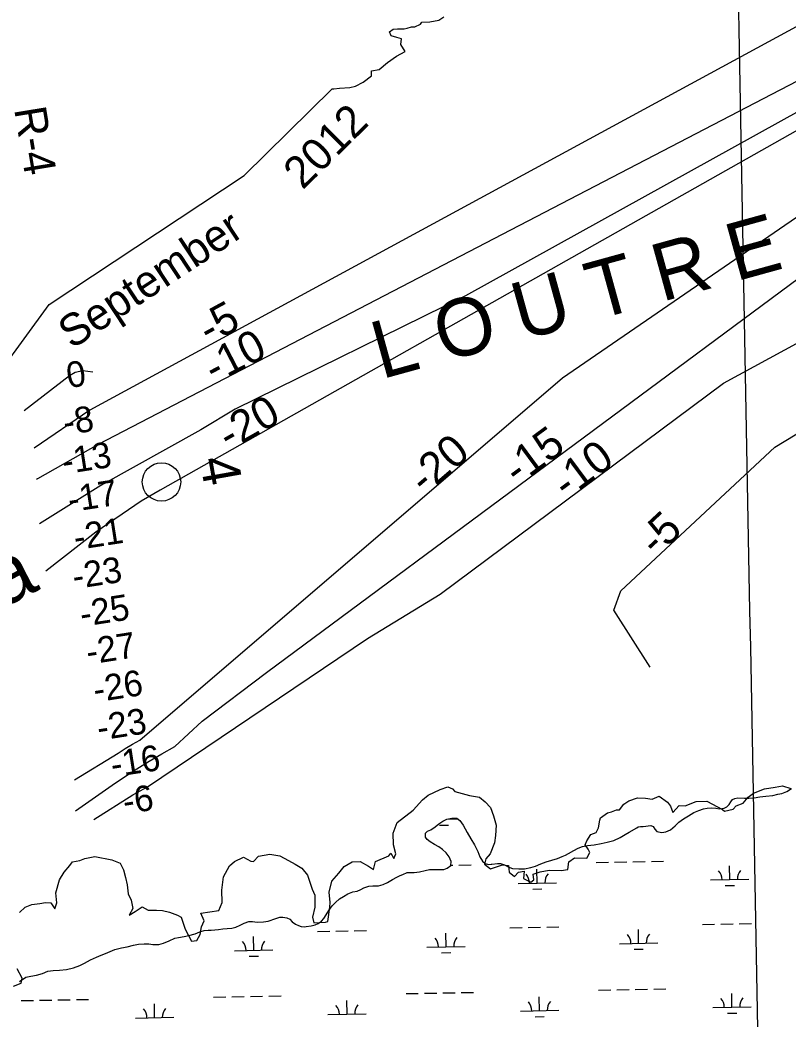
# Model space of a CAD drawing. Extents: x 3957609 to 3995875, y 234277 to 260273.
# Drawn here: x 3965192 to 3967195, y 243942 to 246545 of the extents above; entities that cross this region are included whole.
import ezdxf

# ---------------------------------------------------------------- set-up
doc = ezdxf.new("R2010")
doc.units = 0
for name, color, linetype in [('V-GRID-MAJR', 7, 'Continuous'), ('V-RIVR-EDGE', 7, 'Continuous'), ('V-RIVR-IDEN', 7, 'Continuous'), ('V-RIVR-MILE', 7, 'Continuous'), ('V-RIVR-RANG', 7, 'Continuous'), ('V-RIVR-RANG-IDEN', 7, 'Continuous'), ('V-TOPO-MINR', 7, 'Continuous'), ('V-TOPO-MINR-IDEN', 7, 'Continuous'), ('V-TOPO-WATR', 7, 'Continuous'), ('V-WETL-SWMP', 7, 'Continuous')]:
    doc.layers.add(name, color=color, linetype=linetype)

msp = doc.modelspace()

# ---------------------------------------------------------------- linework, layer by layer
at = {"layer": 'V-GRID-MAJR'}
msp.add_spline([(3967193.104, 239799.451), (3967136.284, 242827.44), (3967022.571, 248887.277), (3966908.859, 254947.105), (3966851.966, 257978.948)], degree=3, dxfattribs=at)
at = {"layer": 'V-RIVR-EDGE'}
for points in [[(3966005.912, 246365.573), (3966010.265, 246366.195), (3966025.234, 246367.858), (3966051.845, 246369.521), (3966066.814, 246372.848), (3966086.773, 246382.827), (3966108.395, 246399.459), (3966108.395, 246412.765), (3966128.354, 246416.092), (3966149.976, 246434.387), (3966173.261, 246451.019), (3966196.546, 246462.662), (3966184.903, 246480.957), (3966186.567, 246495.926), (3966174.924, 246499.253), (3966159.955, 246504.243), (3966154.965, 246514.222), (3966164.945, 246520.875), (3966176.587, 246522.538), (3966193.22, 246522.538), (3966201.536, 246524.201), (3966213.178, 246527.528), (3966221.494, 246527.528), (3966236.464, 246534.181), (3966239.79, 246539.17), (3966260.58, 246540.002), (3966283.866, 246544.992), (3966297.171, 246553.308)], [(3964136.99, 244658.589), (3964156.12, 244665.056), (3964172.018, 244677.72), (3964177.945, 244686.611), (3964517.715, 245044.972), (3964910.025, 245389.861), (3965078.158, 245545.06), (3965267.847, 245803.727), (3965776.558, 246139.993), (3966005.855, 246365.518)], [(3965190.824, 244219.454), (3965205.027, 244232.71), (3965223.017, 244240.285), (3965243.848, 244242.179), (3965258.051, 244245.019), (3965272.254, 244244.072), (3965282.67, 244228.923), (3965288.351, 244244.072), (3965285.511, 244270.585), (3965294.979, 244304.672), (3965307.288, 244324.556), (3965321.491, 244341.6), (3965329.066, 244351.068), (3965348.004, 244354.856), (3965361.26, 244359.59), (3965386.825, 244365.271), (3965431.328, 244356.749), (3965453.106, 244347.281), (3965461.627, 244330.237), (3965467.309, 244310.353), (3965471.096, 244291.416), (3965473.937, 244267.744), (3965481.512, 244251.647), (3965486.246, 244229.87), (3965476.777, 244211.879), (3965491.927, 244221.348), (3965510.864, 244233.657), (3965526.014, 244225.135), (3965547.792, 244225.135), (3965563.889, 244224.188), (3965581.879, 244220.401), (3965602.71, 244211.879), (3965612.179, 244207.145), (3965622.594, 244175.898), (3965638.691, 244144.652), (3965652.894, 244146.545), (3965661.416, 244161.695), (3965665.203, 244181.579), (3965671.831, 244197.676), (3965663.31, 244217.56), (3965710.653, 244224.188), (3965719.175, 244245.019), (3965718.228, 244277.213), (3965722.962, 244312.247), (3965738.112, 244340.653), (3965751.368, 244352.015), (3965775.04, 244363.377), (3965793.977, 244352.962), (3965800.605, 244352.015), (3965813.861, 244366.218), (3965843.214, 244370.952), (3965869.726, 244367.165), (3965892.451, 244354.856), (3965909.495, 244345.387), (3965926.538, 244334.972), (3965941.688, 244316.034), (3965953.997, 244280.053), (3965960.625, 244263.957), (3965960.625, 244232.71), (3965954.944, 244207.145), (3965957.785, 244191.995), (3965988.084, 244193.889), (3965994.712, 244195.782), (3965999.447, 244232.71), (3966000.394, 244245.019), (3965998.5, 244272.478), (3966005.128, 244300.884), (3966023.118, 244321.715), (3966037.321, 244338.759), (3966058.152, 244351.068), (3966078.983, 244352.015), (3966100.761, 244339.706), (3966114.017, 244331.184), (3966118.752, 244352.015), (3966153.786, 244367.165), (3966158.52, 244373.793), (3966167.042, 244359.59), (3966171.776, 244371.899), (3966166.095, 244395.571), (3966165.148, 244425.871), (3966175.564, 244453.33), (3966217.226, 244485.523), (3966241.844, 244512.982), (3966256.047, 244525.291), (3966287.294, 244539.494), (3966307.178, 244547.069), (3966319.487, 244541.388), (3966326.115, 244534.76), (3966363.99, 244524.345), (3966390.502, 244519.61), (3966404.705, 244507.301), (3966418.908, 244493.098), (3966426.483, 244471.32), (3966433.111, 244446.702), (3966432.164, 244420.189), (3966429.323, 244400.305), (3966417.961, 244371.899), (3966406.599, 244358.643), (3966402.811, 244345.387), (3966418.908, 244333.078), (3966450.155, 244343.493), (3966465.304, 244341.6), (3966467.198, 244324.556), (3966481.401, 244313.194), (3966491.817, 244324.556), (3966506.966, 244326.45), (3966505.073, 244307.512), (3966524.01, 244298.044), (3966531.585, 244304.672), (3966529.691, 244318.875), (3966548.628, 244325.503), (3966571.353, 244329.29), (3966602.6, 244328.343), (3966620.59, 244331.184), (3966623.431, 244351.068), (3966637.634, 244361.484), (3966669.827, 244360.537), (3966677.402, 244375.687), (3966673.654, 244384.121)], [(3966673.649, 244384.181), (3966666.04, 244395.571), (3966669.827, 244405.986), (3966680.243, 244422.083), (3966694.446, 244427.764), (3966700.127, 244440.074), (3966703.914, 244459.958), (3966705.808, 244465.639), (3966723.799, 244478.895), (3966734.214, 244481.736), (3966747.47, 244486.47), (3966755.045, 244486.47), (3966766.407, 244501.62), (3966779.664, 244510.142), (3966802.388, 244517.716), (3966823.219, 244516.77), (3966840.263, 244514.876), (3966858.253, 244522.451), (3966880.031, 244506.354), (3966888.553, 244495.939), (3966894.234, 244479.842), (3966910.331, 244497.832), (3966926.428, 244496.885), (3966954.834, 244508.248), (3966983.24, 244509.195), (3967023.955, 244487.417), (3967028.689, 244483.629), (3967051.414, 244488.364), (3967058.989, 244496.885), (3967077.926, 244504.46), (3967090.235, 244519.61), (3967104.438, 244530.026), (3967132.844, 244541.388), (3967161.25, 244546.122), (3967180.187, 244548.963), (3967201.965, 244542.335)], [(3965174.727, 244027.24), (3965194.611, 244034.815), (3965197.452, 244048.071), (3965184.196, 244072.69)]]:
    msp.add_lwpolyline(points, dxfattribs=at)
at = {"layer": 'V-RIVR-MILE'}
msp.add_circle((3965560.875, 245341.194), 50, dxfattribs=at)
at = {"layer": 'V-TOPO-MINR'}
for points in [[(3968181.084, 247052.195), (3965373.926, 245528.563), (3965228.884, 245429.671)], [(3968096.001, 246842.324), (3965395.806, 245438.803), (3965237.649, 245349.708), (3965234.899, 245347.738)], [(3968197.612, 246811.081), (3965557.117, 245319.444), (3965507.466, 245290.941), (3965389.501, 245210.055), (3965258.871, 245108.954)], [(3968102.887, 246796.068), (3966353.197, 245826.642), (3965752.679, 245530.856), (3965663.169, 245477.445), (3965402.799, 245332.334), (3965242.482, 245232.395)], [(3965334.242, 244565.003), (3965447.5, 244634.66), (3965466.336, 244646.125), (3965485.243, 244657.472), (3965504.253, 244668.644), (3966606.154, 245612.18), (3967724.041, 246379.376), (3967996.583, 246490.295), (3968090.356, 246510.845)], [(3965336.203, 244483.843), (3965432.433, 244550.968), (3965464.151, 244572.47), (3965496.234, 244593.396), (3965528.864, 244613.459), (3965561.858, 244632.947), (3965595.241, 244651.79), (3965666.539, 244717.388), (3965834.719, 244844.984), (3967345.253, 245963.426), (3967871.86, 246268.456), (3968018.214, 246314.387)], [(3965384.711, 244461.903), (3965486.509, 244525.473), (3965495.836, 244531.125), (3965505.26, 244536.606), (3965514.828, 244541.832), (3965524.491, 244546.886), (3966098.023, 244932.795), (3966287.417, 245048.337), (3967026.516, 245598.315), (3967816.428, 246028.129), (3967984.26, 246085.689)], [(3966834.79, 244858.74), (3966740.115, 245006.742), (3966758.593, 245057.58), (3967160.478, 245431.935), (3967617.795, 245709.235), (3967862.622, 245806.289), (3967993.694, 245839.928)]]:
    msp.add_lwpolyline(points, dxfattribs=at)
at = {"layer": 'V-TOPO-WATR'}
msp.add_lwpolyline([(3965202.7, 245527.494), (3965320.783, 245618.904), (3965335.436, 245627.527), (3965355.709, 245631.981), (3965381.601, 245628.133)], dxfattribs=at)
at = {"layer": 'V-WETL-SWMP'}
for p, q in [((3966285.366, 244446.642), (3966309.362, 244447.078)), ((3966304.097, 244462.416), (3966333.362, 244462.948)), ((3966314.998, 244342.523), (3966320.419, 244342.622)), ((3966336.416, 244342.913), (3966368.411, 244343.495)), ((3966694.265, 244349.42), (3966726.259, 244350.001)), ((3966742.257, 244350.292), (3966774.252, 244350.874)), ((3966790.249, 244351.165), (3966822.244, 244351.747)), ((3966838.241, 244352.038), (3966870.236, 244352.619)), ((3967042.446, 244305), (3967041.791, 244340.994)), ((3966540.621, 244295.876), (3966539.966, 244331.87)), ((3966490.629, 244294.967), (3966590.613, 244296.785)), ((3966992.454, 244304.091), (3967092.438, 244305.909)), ((3967030.728, 244289.354), (3967054.724, 244289.79)), ((3966528.903, 244280.229), (3966552.899, 244280.665)), ((3966469.323, 244179.128), (3966501.318, 244179.71)), ((3966517.316, 244180.001), (3966549.31, 244180.582)), ((3966565.308, 244180.873), (3966597.302, 244181.455)), ((3966971.149, 244188.253), (3967003.143, 244188.835)), ((3967019.141, 244189.125), (3967051.135, 244189.707)), ((3967067.133, 244189.998), (3967099.127, 244190.58)), ((3965801.306, 244120.544), (3965800.652, 244156.538)), ((3965967.498, 244170.003), (3965999.493, 244170.585)), ((3966015.491, 244170.876), (3966047.485, 244171.458)), ((3966063.483, 244171.749), (3966095.477, 244172.33)), ((3966303.131, 244129.669), (3966302.477, 244165.663)), ((3966804.956, 244138.793), (3966804.302, 244174.787)), ((3966253.139, 244128.76), (3966353.123, 244130.578)), ((3966754.965, 244137.884), (3966854.948, 244139.702)), ((3965751.314, 244119.635), (3965851.298, 244121.453)), ((3965789.589, 244104.897), (3965813.585, 244105.334)), ((3966291.414, 244114.022), (3966315.41, 244114.458)), ((3966793.239, 244123.147), (3966817.235, 244123.583)), ((3965696.663, 243998.55), (3965728.657, 243999.132)), ((3965744.655, 243999.423), (3965776.649, 244000.005)), ((3965792.647, 244000.296), (3965824.642, 244000.877)), ((3965840.639, 244001.168), (3965872.634, 244001.75)), ((3966198.488, 244007.675), (3966230.482, 244008.257)), ((3966246.48, 244008.548), (3966278.475, 244009.129)), ((3966294.472, 244009.42), (3966326.467, 244010.002)), ((3966342.464, 244010.293), (3966374.459, 244010.875)), ((3966546.669, 243963.256), (3966546.014, 243999.25)), ((3966700.313, 244016.8), (3966732.308, 244017.381)), ((3966748.305, 244017.672), (3966780.3, 244018.254)), ((3966796.297, 244018.545), (3966828.292, 244019.127)), ((3966844.289, 244019.418), (3966876.284, 244019.999)), ((3967048.494, 243972.38), (3967047.839, 244008.374)), ((3965194.838, 243989.425), (3965226.832, 243990.007)), ((3965242.83, 243990.298), (3965274.824, 243990.88)), ((3965290.822, 243991.171), (3965322.817, 243991.753)), ((3965338.814, 243992.043), (3965370.809, 243992.625)), ((3965543.019, 243945.006), (3965542.364, 243981)), ((3966044.844, 243954.131), (3966044.189, 243990.125)), ((3966998.502, 243971.471), (3967098.486, 243973.289)), ((3965493.027, 243944.097), (3965593.01, 243945.915)), ((3965994.852, 243953.222), (3966094.836, 243955.04)), ((3966496.677, 243962.347), (3966596.661, 243964.165)), ((3966534.951, 243947.609), (3966558.947, 243948.045)), ((3967036.776, 243956.734), (3967060.772, 243957.17))]:
    msp.add_line(p, q, dxfattribs=at)
for points in [[(3966816.722, 244443.577), (3966836.739, 244445.781), (3966842.498, 244443.138), (3966847.107, 244435.961), (3966852.302, 244430.147), (3966865.29, 244427.894), (3966875.976, 244429.08), (3966887.817, 244434.349), (3966900.04, 244445.349), (3966910.18, 244454.213), (3966922.129, 244462.95), (3966934.988, 244471.245), (3966948.75, 244479.702), (3966961.947, 244484.987), (3966974.553, 244489.361), (3966983.574, 244491.129), (3966994.419, 244491.563), (3967006.18, 244491.104), (3967015.54, 244489.711), (3967027.734, 244490.764), (3967035.076, 244494.32), (3967041.329, 244500.576), (3967045.616, 244507.41), (3967050.217, 244513.193), (3967055.755, 244516.275), (3967063.721, 244518.03), (3967080.908, 244517.486), (3967092.814, 244517.481), (3967106.518, 244518.251), (3967121.11, 244520.389), (3967136.914, 244522.089), (3967154.819, 244524.418), (3967167.895, 244527.29), (3967178.118, 244529.374), (3967191.313, 244534.81), (3967203.884, 244542.047)], [(3965925.481, 244182.665), (3965933.625, 244182.162), (3965937.991, 244182.516), (3965950.783, 244184.029), (3965961.599, 244186.874), (3965969.388, 244190.737), (3965977.762, 244196.114), (3965984.151, 244203.576), (3965990.36, 244213.448), (3965996.854, 244224.68), (3966005.602, 244236.391), (3966014.231, 244245.539), (3966025.271, 244254.716), (3966035.594, 244260.87), (3966046.965, 244267.64), (3966059.712, 244272.769), (3966071.138, 244275.019), (3966080.28, 244279.199), (3966088.671, 244283.22), (3966101.427, 244287.596), (3966111.515, 244288.322), (3966126.583, 244288.506), (3966139.204, 244291.675), (3966150.435, 244297.539), (3966163.458, 244304.781), (3966174.535, 244310.944), (3966183.07, 244315.419), (3966189.816, 244318.365), (3966201.512, 244323.18), (3966209.044, 244323.423), (3966219.289, 244323.698), (3966233.282, 244325.527), (3966248.467, 244328.426), (3966259.741, 244330.824), (3966268.626, 244331.385), (3966282.042, 244331.096), (3966296.959, 244331.279), (3966305.963, 244334.403), (3966314.914, 244341.897), (3966316.296, 244352.162), (3966311.029, 244363.852), (3966303.366, 244374.308), (3966293.31, 244383.227), (3966284.181, 244390.349), (3966272.955, 244396.391), (3966261.872, 244403.037), (3966253.809, 244409.268), (3966249.209, 244415.692), (3966249.084, 244425.939), (3966254.602, 244430.678), (3966262.842, 244434.697), (3966274.201, 244442.371), (3966283.896, 244450.628), (3966294.06, 244457.534), (3966304.547, 244462.635), (3966318.079, 244465.212), (3966330.743, 244464.764), (3966338.647, 244459.284), (3966347.24, 244446.73), (3966357.869, 244427.871), (3966367.566, 244411.262), (3966377.249, 244395.857), (3966386.055, 244378.182), (3966390.594, 244364.373), (3966398.121, 244352.71), (3966404.823, 244346.914), (3966413.148, 244344.002), (3966420.819, 244345.15), (3966422.477, 244345.171), (3966436.623, 244346.851), (3966444.759, 244346.95), (3966455.05, 244343.459), (3966465.216, 244337.856), (3966476.565, 244334.077), (3966492.857, 244332.769), (3966507.319, 244333.247), (3966523.555, 244336.46), (3966536.323, 244339.931), (3966550.27, 244345.527), (3966563.765, 244351.117), (3966578.93, 244355.673), (3966593.495, 244360.071), (3966605.492, 244364.889), (3966614.039, 244368.46), (3966622.424, 244372.933), (3966636.343, 244380.789), (3966647.12, 244386.798), (3966658.521, 244391.157), (3966671.303, 244393.423), (3966688.756, 244395.746), (3966707.104, 244398.834), (3966722.738, 244402.039), (3966740.16, 244406.924), (3966756.493, 244414.659), (3966769.659, 244422.506), (3966780.736, 244428.669), (3966800.489, 244440.063), (3966803.78, 244442.062), (3966809.64, 244443.49), (3966816.722, 244443.577)], [(3965190.286, 244039.552), (3965206.734, 244050.152), (3965219.81, 244053.024), (3965235.301, 244055.625), (3965250.163, 244060.328), (3965264.711, 244066.082), (3965278.096, 244068.355), (3965294.974, 244068.411), (3965313.032, 244070.59), (3965331.662, 244075.339), (3965348.02, 244080.965), (3965360.3, 244087.294), (3965375.868, 244095.923), (3965391.007, 244102.589), (3965403.903, 244107.87), (3965414.848, 244112.525), (3965439.585, 244123.075), (3965456.568, 244126.9), (3965471.451, 244129.945), (3965487.829, 244133.913), (3965501.059, 244136.486), (3965515.813, 244137.721), (3965527.877, 244137.115), (3965537.842, 244135.579), (3965553.965, 244135.776), (3965566.433, 244139.093), (3965580.52, 244145.595), (3965595.211, 244151.954), (3965605.132, 244154.034), (3965619.574, 244156.17), (3965632.35, 244158.888), (3965648.422, 244163.304), (3965660.416, 244168.424), (3965672.126, 244172.033), (3965682.966, 244172.919), (3965690.046, 244173.156), (3965709.472, 244174.449), (3965720.749, 244176.546), (3965731.89, 244177.435), (3965744.393, 244177.89), (3965754.757, 244180.729), (3965765.841, 244186.29), (3965776.028, 244191.237), (3965788.485, 244195.458), (3965798.581, 244195.582), (3965810.353, 244194.218), (3965826.622, 244194.719), (3965839.112, 244196.228), (3965858.916, 244203.553), (3965869.124, 244206.842), (3965877.564, 244206.795), (3965887.828, 244205.413), (3965895.561, 244201.589), (3965901.671, 244194.882), (3965910.486, 244188.811), (3965918.066, 244185.136), (3965925.481, 244182.665)]]:
    msp.add_lwpolyline(points, dxfattribs=at)
for centre, start, end in [((3966352.308, 244463.768), 177.959465, 181.813534), ((3966485.378, 244295.346), 0.269879, 41.813537), ((3966595.846, 244297.355), 140.269876, 181.813534), ((3966987.203, 244304.471), 0.269879, 41.813537), ((3967097.671, 244306.479), 140.269876, 181.813534), ((3966247.889, 244129.139), 0.269879, 41.813537), ((3966358.356, 244131.148), 140.269876, 181.813534), ((3966749.714, 244138.264), 0.269879, 41.813537), ((3966860.181, 244140.272), 140.269876, 181.813534), ((3965746.064, 244120.014), 0.269879, 41.813537), ((3965856.531, 244122.023), 140.269876, 181.813534), ((3966993.251, 243971.851), 0.269879, 41.813537), ((3967103.719, 243973.859), 140.269876, 181.813534), ((3965598.244, 243946.485), 140.269876, 181.813534), ((3965989.601, 243953.601), 0.269879, 41.813537), ((3966100.069, 243955.61), 140.269876, 181.813534), ((3966491.426, 243962.726), 0.269879, 41.813537), ((3966601.894, 243964.735), 140.269876, 181.813534), ((3965487.776, 243944.477), 0.269879, 41.813537)]:
    msp.add_arc(centre, 35.246, start, end, dxfattribs=at)

# ---------------------------------------------------------------- texts
at = {"layer": 'V-RIVR-IDEN'}
for s, height, rotation, p in [('2012', 82.9998, 44.524809, (3965928.961, 246100.927)), ('September', 82.9998, 33.465379, (3965327.387, 245685.867)), ('L O U T R E', 149.9997, 15.425472, (3966134.294, 245608.538)), ('4', 100, 280.166716, (3965660.198, 245399.779)), ('a', 150, 27.002011, (3965147.039, 245011.79))]:
    msp.add_text(s, height=height, rotation=rotation, dxfattribs=at).set_placement(p)
at = {"layer": 'V-RIVR-RANG'}
for s, p in [('0', (3965318.32, 245585.45)), ('-8', (3965309.216, 245462.656)), ('-13', (3965306.202, 245360.88)), ('-17', (3965321.718, 245262.014)), ('-21', (3965336.903, 245163.14)), ('-23', (3965333.581, 245061.535)), ('-25', (3965353.205, 244963.488)), ('-27', (3965369.386, 244864.799)), ('-26', (3965388.049, 244766.432)), ('-23', (3965397.681, 244666.805)), ('-16', (3965433.36, 244571.186)), ('-6', (3965465.038, 244474.827))]:
    msp.add_text(s, height=67, rotation=8.840389, dxfattribs=at).set_placement(p)
at = {"layer": 'V-RIVR-RANG-IDEN'}
msp.add_text('R-4 ', height=83, rotation=279.309328, dxfattribs=at).set_placement((3965176.399, 246313.135))
at = {"layer": 'V-TOPO-MINR-IDEN'}
for s, rotation, p in [('-5', 28.491631, (3965684.658, 245697.218)), ('-10', 27.464736, (3965698.42, 245596.097)), ('-20', 29.46246, (3965736.95, 245421.033)), ('-15', 36.517308, (3966489.808, 245330.031)), ('-20', 40.572797, (3966247.973, 245305.477)), ('-10', 36.653649, (3966617.636, 245294.059)), ('-5', 42.968778, (3966851.1, 245143.75))]:
    msp.add_text(s, height=83, rotation=rotation, dxfattribs=at).set_placement(p)

doc.saveas('drawing.dxf')
